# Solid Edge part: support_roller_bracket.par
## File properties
Title: Support roller bracket
Author: vicky raina
Template: Normal.par
Last saved by: Robert a Rhodes jr
Revision: 15
Application: Solid Edge
Material: aluminum
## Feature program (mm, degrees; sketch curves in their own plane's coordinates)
sketch for "unnamed Protrusion 1" #1 plane through (0, 0, 0) normal (0, -1, 0) x-axis (1, 0, 0)
  circle centre (0, -138.9237) radius 3.81
sketch for "unnamed Protrusion 1" #2 plane through (0, 0, 0) normal (0, -1, 0) x-axis (1, 0, 0)
  line (143.637, -99.9249) -> (-143.637, -99.9249)
  line (-143.637, -99.9249) -> (-143.637, -115.1647)
  line (-143.637, -115.1647) -> (-61.0846, -156.7704)
  line (-61.0846, -156.7704) -> (-61.0846, -162.9363)
  line (-61.0846, -162.9363) -> (61.0846, -162.9363)
  line (61.0846, -156.7704) -> (61.0846, -162.9363)
  line (143.637, -115.1647) -> (61.0846, -156.7704)
  line (143.637, -99.9249) -> (143.637, -115.1647)
  dimension (linear) = 143.637
extrude "unnamed Protrusion 1" add finite 101.6 symmetric
fillet "unnamed Round 1"
fillet "unnamed Round 2"
sketch for "unnamed Protrusion 2" plane through (0, 0, 67.2512) normal (1, 0, 0) x-axis (0, 1, 0)
  arc centre (-23.4135, -61.792) radius 19.05 from (-23.4135, -42.742) to (-42.405, -60.3002) ccw
  line (-50.8, -167.1761) -> (-42.405, -60.3002)
  line (-50.8, -167.1761) -> (50.8, -167.1761)
  line (45.7777, -60.8928) -> (50.8, -167.1761)
  arc centre (26.749, -61.792) radius 19.05 from (26.749, -42.742) to (45.7777, -60.8928) cw
  line (19.05, -42.742) -> (26.749, -42.742)
  line (19.05, -64.967) -> (19.05, -42.742)
  arc centre (0, -64.967) radius 19.05 from (-19.05, -64.967) to (19.05, -64.967) ccw
  line (-19.05, -42.742) -> (-19.05, -64.967)
  line (-23.4135, -42.742) -> (-19.05, -42.742)
extrude "unnamed Protrusion 2" add to key point symmetric
sketch for "unnamed Cutout 1" plane through (0, 0, 0) normal (0, -1, 0) x-axis (1, 0, 0)
  line (-128.3193, 24.5092) -> (125.6319, 24.5092)
  line (125.6319, 24.5092) -> (125.6319, -99.9249)
  line (125.6319, -99.9249) -> (-128.3193, -99.9249)
  line (-128.3193, -99.9249) -> (-128.3193, 24.5092)
extrude "unnamed Cutout 1" cut finite 203.2 symmetric
chamfer "unnamed Chamfer 1"
rib "unnamed Rib 1"
mirror "unnamed Mirror 1" of "unnamed Rib 1" about plane through (0, 0, 0) normal (1, 0, 0)
rib "unnamed Rib 2"
sketch for "unnamed Hole 1" plane through (0.1259, 0, -162.9363) normal (0, 0, -1) x-axis (-1, 0, 0)
  hole centre (0.1259, 0) bore radius 25.4
hole "unnamed Hole 1" through
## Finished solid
Body 1: solid body, 55 faces, 142 edges, 86 vertices.
  Faces by surface: plane 38, cylinder 17
  Edges by curve: line 106, circle 34, intersection 2
Bounding box of the edges (mm): 379.121 x 101.600 x 187.446, from (-189.5605, -50.8, -162.9363) to (189.5605, 50.8, 24.5092).
Cylindrical faces by radius (mm): R3.81 x2, R6.35 x2, R19.05 x6, R25.4 x1, R31.75 x4, R55.372 x2
Planar faces by outward normal: +x 4, +y 5, +z 5, -x 4, -y 5, -z 1, oblique 14
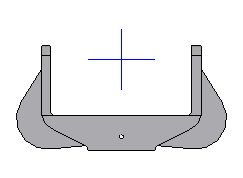
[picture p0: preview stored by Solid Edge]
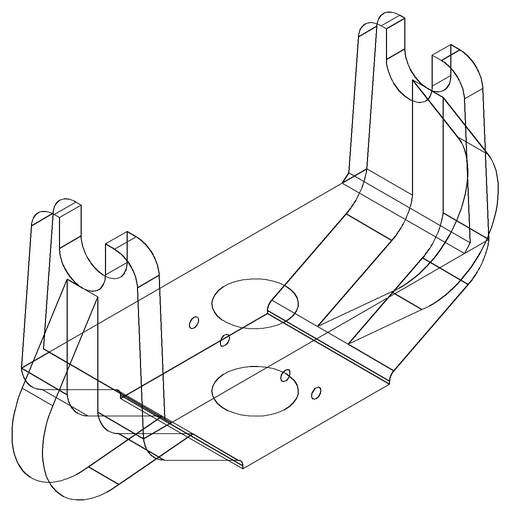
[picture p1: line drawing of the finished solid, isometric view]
